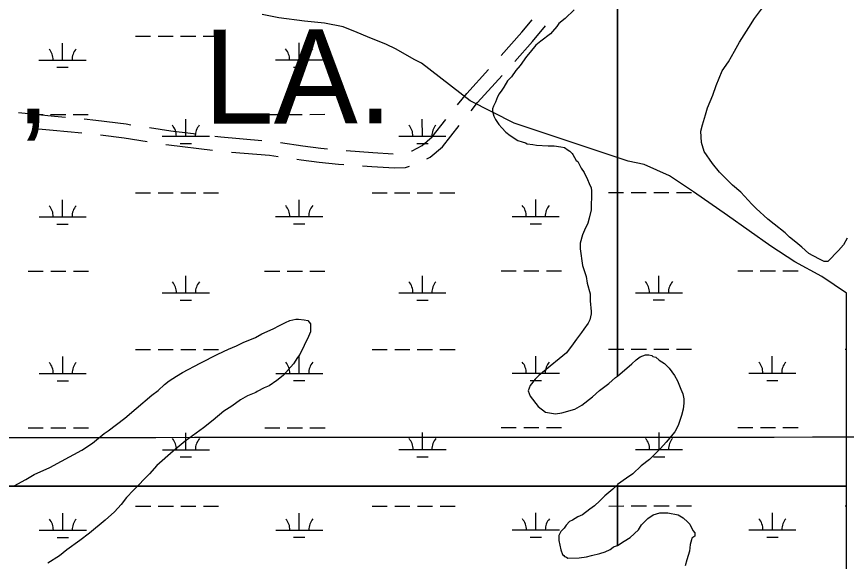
# Model space of a CAD drawing. Extents: x 3279314 to 3317160, y 734079 to 759431.
# Drawn here: x 3299638 to 3301399, y 745259 to 746416 of the extents above; entities that cross this region are included whole.
import ezdxf

# ---------------------------------------------------------------- set-up
doc = ezdxf.new("R2010")
doc.units = 0
for name, color, linetype in [('V-GRID-MAJR', 7, 'Continuous'), ('V-ROAD-CNTR', 7, 'Continuous'), ('V-SITE-VEGE', 7, 'Continuous'), ('V-TOPO-GNAM-IDEN', 7, 'Continuous'), ('V-WETL-SWMP', 7, 'Continuous')]:
    doc.layers.add(name, color=color, linetype=linetype)

msp = doc.modelspace()

# ---------------------------------------------------------------- linework, layer by layer
at = {"layer": 'V-GRID-MAJR'}
msp.add_spline([(3283456.6, 745517.7), (3286079.8, 745518), (3291326.2, 745519.1), (3296572.6, 745521), (3301819.1, 745523.7), (3307065.5, 745527.1), (3312312, 745531.3), (3314935.2, 745533.7)], degree=3, dxfattribs=at)
at = {"layer": 'V-ROAD-CNTR'}
for points in [[(3300666.3, 746333.6), (3300710.1, 746382.6), (3300731.9, 746409.1)], [(3300695.1, 746320.9), (3300732.8, 746363.1), (3300760.4, 746396.5)], [(3300573.9, 746228.5), (3300593.6, 746252.8), (3300639.6, 746303.9)], [(3300602.4, 746216), (3300616.4, 746233.3), (3300668.4, 746291.1)], [(3299642.2, 746212.2), (3299718.8, 746204.7), (3299741.7, 746202.5)], [(3299781.5, 746198.6), (3299806.1, 746196.3), (3299870.4, 746188), (3299880.7, 746186.4)], [(3300476.2, 746130.9), (3300477.2, 746131.2), (3300498.6, 746142.5), (3300519.9, 746160.3), (3300548.9, 746197.2)], [(3299677.1, 746178.6), (3299715.9, 746174.8), (3299776.6, 746169)], [(3299920.3, 746180.2), (3299965.1, 746173.2), (3300019.3, 746166.7)], [(3300508.3, 746113.7), (3300515.4, 746117.4), (3300541.6, 746139.3), (3300577.3, 746184.8)], [(3299816.3, 746164.7), (3299866.2, 746158.3), (3299915.3, 746150.6)], [(3300059, 746161.9), (3300071.6, 746160.4), (3300158.6, 746153)], [(3299954.8, 746144.4), (3299961, 746143.5), (3300054.1, 746132.3)], [(3300198.3, 746148.4), (3300245.7, 746141.5), (3300283.7, 746136.8), (3300297.5, 746135.4)], [(3300093.9, 746128.4), (3300174.6, 746121.6), (3300193.4, 746118.8)], [(3300337.3, 746131.8), (3300393.9, 746127.5), (3300437, 746124.8)], [(3300233, 746113), (3300241.7, 746111.8), (3300280.4, 746107), (3300320.9, 746102.9), (3300332.3, 746102.1)], [(3300372.2, 746099.1), (3300391.8, 746097.6), (3300439.7, 746094.6), (3300463.6, 746095.6), (3300471.7, 746098.1)]]:
    msp.add_lwpolyline(points, dxfattribs=at)
at = {"layer": 'V-SITE-VEGE'}
for points in [[(3300822.9, 745582.3), (3300837.5, 745590.7), (3300860.3, 745608.6), (3300874.9, 745622.2), (3300894.6, 745636.9), (3300909.1, 745649.4), (3300912.9, 745652.7), (3300912.9, 746541)], [(3300912.9, 746541), (3300912.9, 745652.7), (3300943.4, 745678.8), (3300952.7, 745687.2), (3300961, 745693.5), (3300972.4, 745697.7), (3300979.7, 745697.7), (3300986, 745696.7), (3300988.1, 745694.6), (3300994.4, 745692.6), (3301001.7, 745686.4), (3301013.2, 745679.1), (3301022.6, 745669.8), (3301034.1, 745654.2), (3301040.4, 745642.8), (3301047.8, 745625.1), (3301052, 745614.7), (3301054.2, 745604.3), (3301054.2, 745594.9), (3301052.2, 745582.4), (3301049.1, 745568.8), (3301041.9, 745548), (3301034.7, 745534.4), (3301016.1, 745512.4), (3301004.7, 745498.8), (3300980.8, 745475.8), (3300963.2, 745462.1), (3300945.5, 745445.4), (3300932, 745435.9), (3300913.3, 745422.3), (3300912.9, 745421.9), (3300912.9, 745293.3), (3300927.4, 745302.5), (3300939.9, 745309.9), (3300957.6, 745326.6), (3300963.8, 745337.1), (3300977.2, 745350.7), (3300988.7, 745358), (3301003.2, 745362.3), (3301019.9, 745362.4), (3301041.8, 745358.3), (3301052.3, 745352.1), (3301062.7, 745342.8), (3301066.9, 745338.6), (3301073.2, 745325.1), (3301077.4, 745319.9), (3301077.5, 745312.6), (3301071.2, 745308.4), (3301070.2, 745305.3), (3301067.1, 745294.9), (3301066.1, 745281.3), (3301060, 745262.5), (3301056.9, 745250)], [(3300821, 746430.6), (3300802.3, 746411.7), (3300788.8, 746401.2), (3300784.7, 746395), (3300775.3, 746384.5), (3300771.2, 746379.3), (3300750.4, 746363.5), (3300740, 746355.2), (3300727.6, 746340.5), (3300720.4, 746331.1), (3300706.9, 746312.3), (3300697.6, 746301.8), (3300688.3, 746288.2), (3300680, 746279.8), (3300671.7, 746266.3), (3300667.6, 746260), (3300662.4, 746251.6), (3300658.2, 746245.3), (3300654.1, 746233.9), (3300650, 746225.5), (3300647.9, 746220.3), (3300648, 746215.1), (3300651.1, 746204.7), (3300654.3, 746197.4), (3300661.6, 746187), (3300667.9, 746179.7), (3300676.3, 746170.4), (3300685.7, 746163.2), (3300701.4, 746152.8), (3300710.8, 746149.7), (3300718.1, 746147.7), (3300721.2, 746145.6), (3300733.8, 746144.6), (3300741.1, 746142.6), (3300766.1, 746141.7), (3300778.6, 746141.7), (3300793.2, 746139.7), (3300800.5, 746137.7), (3300808.8, 746132.5), (3300812, 746130.4), (3300817.2, 746125.2), (3300818.3, 746123.2), (3300825.6, 746110.7), (3300828.8, 746108.6), (3300836.1, 746094.1), (3300842.4, 746084.7), (3300849.8, 746070.2), (3300852.9, 746061.8), (3300857.2, 746052.5), (3300858.2, 746046.2), (3300858.3, 746030.6), (3300857.3, 746019.1), (3300857.4, 746005.6), (3300853.3, 745987.8), (3300850.2, 745977.4), (3300843, 745962.8), (3300838.9, 745952.3), (3300833.8, 745934.6), (3300833.8, 745923.1), (3300839.2, 745887.7), (3300846.6, 745863.8), (3300848.8, 745850.3), (3300855.1, 745827.4), (3300855.2, 745812.8), (3300857.4, 745789.9), (3300857.4, 745784.7), (3300854.3, 745772.1), (3300851.2, 745764.8), (3300841.9, 745752.3), (3300836.8, 745745), (3300826.4, 745731.4), (3300819.2, 745720.9), (3300804.7, 745702.1), (3300789.1, 745689.5), (3300770.4, 745673.8), (3300762.1, 745666.5), (3300746.5, 745653.9), (3300738.2, 745646.5), (3300727.9, 745632.9), (3300723.8, 745621.5), (3300728, 745610), (3300744.8, 745588.2), (3300760.5, 745575.8), (3300781.3, 745572.8), (3300794.8, 745574.9), (3300822.9, 745582.3)], [(3301400.5, 745945.2), (3301392.6, 745931.7), (3301382, 745919.4), (3301359.5, 745896.3), (3301351.4, 745896.2), (3301343.3, 745900.1), (3301328.4, 745908), (3301318.9, 745913.2), (3301304, 745926.5), (3301291.7, 745937.1), (3301278.2, 745947.7), (3301268.6, 745957), (3301245.6, 745975.5), (3301232, 745986.1), (3301207.5, 746008.6), (3301198, 746017.9), (3301174.8, 746043.2), (3301157.1, 746057.7), (3301129.9, 746085.6), (3301114.9, 746104.2), (3301097.1, 746129.6), (3301091.5, 746148.3), (3301089.8, 746172.5), (3301093.7, 746186), (3301100.1, 746207.6), (3301104, 746222.4), (3301115.7, 746249.4), (3301122.2, 746269.7), (3301135.2, 746300.8), (3301148.5, 746319.8), (3301161.6, 746342.8), (3301172.1, 746361.7), (3301191.9, 746392.9), (3301203.7, 746411.9), (3301224.9, 746440.4)], [(3299990.2, 745660.1), (3300027.6, 745680.1), (3300065, 745699), (3300087.9, 745709.6), (3300104.5, 745716.9), (3300119.1, 745724.3), (3300145.1, 745734.8), (3300158.6, 745742.2), (3300182.5, 745752.7), (3300196, 745760.1), (3300208.5, 745766.4), (3300217.9, 745770.6), (3300230.3, 745773.8), (3300236.6, 745773.8), (3300248.1, 745771.8), (3300256.4, 745770.8), (3300261.7, 745763.5), (3300261.7, 745746.9), (3300257.6, 745736.4), (3300239, 745698.8), (3300233.9, 745692.5), (3300225.6, 745679), (3300203.8, 745653.8), (3300190.3, 745643.4), (3300173.7, 745631.8), (3300163.3, 745627.6), (3300148.8, 745620.2), (3300145.6, 745618.1), (3300128, 745610.7), (3300113.4, 745602.3), (3300094.7, 745588.7), (3300078.1, 745578.2), (3300055.3, 745559.3), (3300034.5, 745542.6), (3299996.1, 745514.2), (3299970.1, 745493.3), (3299935.9, 745462.9), (3299920.3, 745445.1), (3299886.1, 745410.6), (3299871.6, 745394.9), (3299860.2, 745380.2), (3299845.7, 745364.5), (3299826, 745346.7), (3299792.8, 745319.4), (3299772, 745303.7), (3299745, 745283.8), (3299729.4, 745271.2), (3299704.5, 745255.5)], [(3299632.9, 745419.8), (3299657.8, 745433.4), (3299675.5, 745443.9), (3299708.7, 745458.7), (3299733.7, 745472.3), (3299776.3, 745495.5), (3299799.1, 745510.2), (3299824.1, 745531.1), (3299832.4, 745536.4), (3299867.7, 745563.6), (3299891.5, 745583.6), (3299924.8, 745611.9), (3299938.2, 745622.3), (3299951.7, 745634.9), (3299962.1, 745642.3), (3299977.7, 745652.8), (3299990.2, 745660.1)]]:
    msp.add_lwpolyline(points, dxfattribs=at)
msp.add_lwpolyline([(3300912.9, 745421.9), (3300903, 745412.9), (3300886.3, 745398.2), (3300876, 745387.7), (3300864.6, 745377.3), (3300854.2, 745369.9), (3300838.6, 745358.4), (3300829.2, 745354.2), (3300817.8, 745346.8), (3300811.6, 745343.7), (3300804.3, 745336.3), (3300800.2, 745330.1), (3300792.9, 745322.7), (3300788.8, 745314.4), (3300788.8, 745303.9), (3300793.1, 745284.2), (3300796.3, 745273.8), (3300799.4, 745271.7), (3300800.5, 745269.6), (3300804.6, 745268.6), (3300807.8, 745266.5), (3300831.7, 745266.6), (3300847.4, 745268.8), (3300857.8, 745272), (3300875.5, 745276.2), (3300886.9, 745279.4), (3300897.3, 745284.7), (3300900.4, 745286.8), (3300904.6, 745289.9), (3300910.8, 745292), (3300912.9, 745293.3)], close=True, dxfattribs=at)
at = {"layer": 'V-WETL-SWMP'}
for p, q in [((3299890.2, 746374.4), (3299922.2, 746374.4)), ((3299938.2, 746374.4), (3299970.2, 746374.5)), ((3299986.2, 746374.5), (3300018.2, 746374.5)), ((3300034.2, 746374.5), (3300066.2, 746374.5)), ((3299735.6, 746323.6), (3299735.6, 746359.6)), ((3300237.5, 746323.9), (3300237.5, 746359.9)), ((3299685.6, 746323.6), (3299785.6, 746323.6)), ((3300187.5, 746323.8), (3300287.5, 746323.9)), ((3299723.6, 746308.2), (3299747.6, 746308.2)), ((3300225.6, 746308.4), (3300249.6, 746308.4)), ((3299662.3, 746208.1), (3299694.3, 746208.1)), ((3299710.3, 746208.2), (3299742.3, 746208.2)), ((3299758.3, 746208.2), (3299790.3, 746208.2)), ((3299997.2, 746161.9), (3299997.1, 746197.9)), ((3300164.2, 746208.4), (3300196.2, 746208.4)), ((3300212.2, 746208.4), (3300244.2, 746208.4)), ((3300260.2, 746208.4), (3300292.2, 746208.5)), ((3300499.1, 746162.1), (3300499, 746198.1)), ((3299947.2, 746161.8), (3300047.2, 746161.9)), ((3300449.1, 746162.1), (3300549.1, 746162.2)), ((3299985.2, 746146.4), (3300009.2, 746146.4)), ((3300487.1, 746146.7), (3300511.1, 746146.7)), ((3299890.4, 746041.7), (3299922.4, 746041.8)), ((3299938.4, 746041.8), (3299970.4, 746041.8)), ((3299986.4, 746041.8), (3300018.4, 746041.8)), ((3300034.4, 746041.8), (3300066.4, 746041.8)), ((3300392.3, 746042), (3300424.3, 746042)), ((3300440.3, 746042), (3300472.3, 746042)), ((3300488.3, 746042.1), (3300520.3, 746042.1)), ((3300536.3, 746042.1), (3300568.3, 746042.1)), ((3300894.2, 746042.3), (3300926.2, 746042.3)), ((3300942.2, 746042.3), (3300974.2, 746042.3)), ((3300990.2, 746042.3), (3301022.2, 746042.3)), ((3301038.2, 746042.3), (3301070.2, 746042.3)), ((3299735.8, 745990.9), (3299735.8, 746026.9)), ((3300237.7, 745991.2), (3300237.7, 746027.2)), ((3300739.6, 745991.4), (3300739.6, 746027.4)), ((3299685.8, 745990.9), (3299785.8, 745991)), ((3300187.7, 745991.2), (3300287.7, 745991.2)), ((3300689.6, 745991.4), (3300789.6, 745991.5)), ((3299723.8, 745975.5), (3299747.8, 745975.5)), ((3300225.7, 745975.7), (3300249.7, 745975.8)), ((3300727.6, 745976), (3300751.6, 745976)), ((3299662.5, 745875.5), (3299694.5, 745875.5)), ((3299710.5, 745875.5), (3299742.5, 745875.5)), ((3299758.5, 745875.5), (3299790.5, 745875.5)), ((3299997.3, 745829.2), (3299997.3, 745865.2)), ((3300164.4, 745875.7), (3300196.4, 745875.7)), ((3300212.4, 745875.7), (3300244.4, 745875.8)), ((3300260.4, 745875.8), (3300292.4, 745875.8)), ((3300499.2, 745829.5), (3300499.2, 745865.5)), ((3300666.3, 745876), (3300698.3, 745876)), ((3300714.3, 745876), (3300746.3, 745876)), ((3300762.3, 745876), (3300794.3, 745876)), ((3301001.1, 745829.7), (3301001.1, 745865.7)), ((3301168.2, 745876.2), (3301200.2, 745876.2)), ((3301216.2, 745876.2), (3301248.2, 745876.3)), ((3301264.2, 745876.3), (3301296.2, 745876.3)), ((3299947.3, 745829.2), (3300047.3, 745829.2)), ((3300449.2, 745829.4), (3300549.2, 745829.5)), ((3300951.1, 745829.7), (3301051.1, 745829.7)), ((3299985.3, 745813.8), (3300009.3, 745813.8)), ((3300487.2, 745814), (3300511.2, 745814)), ((3300989.1, 745814.3), (3301013.1, 745814.3)), ((3299890.5, 745709.1), (3299922.5, 745709.1)), ((3299938.5, 745709.1), (3299970.5, 745709.1)), ((3299986.5, 745709.1), (3300018.5, 745709.1)), ((3300034.5, 745709.1), (3300066.5, 745709.2)), ((3300392.4, 745709.3), (3300424.4, 745709.3)), ((3300440.4, 745709.4), (3300472.4, 745709.4)), ((3300488.4, 745709.4), (3300520.4, 745709.4)), ((3300536.4, 745709.4), (3300568.4, 745709.4)), ((3300894.4, 745709.6), (3300926.4, 745709.6)), ((3300942.4, 745709.6), (3300974.4, 745709.6)), ((3300990.4, 745709.6), (3301022.4, 745709.6)), ((3301038.4, 745709.7), (3301070.4, 745709.7)), ((3301396.3, 745709.8), (3301398.9, 745709.8)), ((3299736, 745658.3), (3299736, 745694.3)), ((3300237.9, 745658.5), (3300237.9, 745694.5)), ((3300739.8, 745658.8), (3300739.8, 745694.8)), ((3301241.7, 745659), (3301241.7, 745695)), ((3299686, 745658.2), (3299786, 745658.3)), ((3300187.9, 745658.5), (3300287.9, 745658.5)), ((3300689.8, 745658.7), (3300789.8, 745658.8)), ((3301191.7, 745659), (3301291.7, 745659)), ((3299724, 745642.8), (3299748, 745642.8)), ((3300225.9, 745643.1), (3300249.9, 745643.1)), ((3300727.8, 745643.3), (3300751.8, 745643.3)), ((3301229.7, 745643.6), (3301253.7, 745643.6)), ((3299662.6, 745542.8), (3299694.6, 745542.8)), ((3299710.6, 745542.8), (3299742.6, 745542.8)), ((3299758.6, 745542.8), (3299790.6, 745542.8)), ((3299997.5, 745496.5), (3299997.5, 745532.5)), ((3300164.5, 745543), (3300196.5, 745543.1)), ((3300212.5, 745543.1), (3300244.5, 745543.1)), ((3300260.5, 745543.1), (3300292.5, 745543.1)), ((3300499.4, 745496.8), (3300499.4, 745532.8)), ((3300666.4, 745543.3), (3300698.4, 745543.3)), ((3300714.4, 745543.3), (3300746.4, 745543.3)), ((3300762.4, 745543.3), (3300794.4, 745543.4)), ((3301001.3, 745497), (3301001.3, 745533)), ((3301168.3, 745543.5), (3301200.3, 745543.6)), ((3301216.3, 745543.6), (3301248.3, 745543.6)), ((3301264.3, 745543.6), (3301296.3, 745543.6)), ((3299947.5, 745496.5), (3300047.5, 745496.5)), ((3300449.4, 745496.8), (3300549.4, 745496.8)), ((3300951.3, 745497), (3301051.3, 745497.1)), ((3299985.5, 745481.1), (3300009.5, 745481.1)), ((3300487.4, 745481.3), (3300511.4, 745481.4)), ((3300989.3, 745481.6), (3301013.3, 745481.6)), ((3301398.9, 745419.1), (3294985.1, 745419)), ((3301398.9, 745419.1), (3294985.1, 745419)), ((3301398.9, 744248.6), (3301398.9, 745419.1)), ((3301398.9, 744248.6), (3301398.9, 745419.1)), ((3299890.7, 745376.4), (3299922.7, 745376.4)), ((3299938.7, 745376.5), (3299970.7, 745376.5)), ((3299986.7, 745376.5), (3300018.7, 745376.5)), ((3300034.7, 745376.5), (3300066.7, 745376.5)), ((3300392.6, 745376.7), (3300424.6, 745376.7)), ((3300440.6, 745376.7), (3300472.6, 745376.7)), ((3300488.6, 745376.7), (3300520.6, 745376.7)), ((3300536.6, 745376.8), (3300568.6, 745376.8)), ((3300894.5, 745376.9), (3300926.5, 745377)), ((3300942.5, 745377), (3300974.5, 745377)), ((3300990.5, 745377), (3301022.5, 745377)), ((3301038.5, 745377), (3301070.5, 745377)), ((3301396.4, 745377.2), (3301398.9, 745377.2)), ((3299736.1, 745325.6), (3299736.1, 745361.6)), ((3300238, 745325.9), (3300238, 745361.9)), ((3300739.9, 745326.1), (3300739.9, 745362.1)), ((3301241.8, 745326.4), (3301241.8, 745362.4)), ((3299686.1, 745325.6), (3299786.1, 745325.6)), ((3300188, 745325.8), (3300288, 745325.9)), ((3300689.9, 745326.1), (3300789.9, 745326.1)), ((3301191.8, 745326.3), (3301291.8, 745326.4)), ((3299724.1, 745310.2), (3299748.1, 745310.2)), ((3300226, 745310.4), (3300250, 745310.4)), ((3300727.9, 745310.7), (3300751.9, 745310.7)), ((3301229.8, 745310.9), (3301253.8, 745310.9))]:
    msp.add_line(p, q, dxfattribs=at)
msp.add_lwpolyline([(3294985.1, 745419), (3301398.9, 745419), (3301398.9, 745828.8), (3301346.9, 745864), (3301289.2, 745895.5), (3301238.5, 745928.2), (3301146.5, 745993.6), (3301074.5, 746043.8), (3301023.8, 746077.6), (3300969.6, 746102), (3300935.5, 746108.9), (3300694.1, 746190), (3300600.3, 746237.2), (3300497.2, 746317.2), (3300483.1, 746324.2), (3300441.8, 746347.5), (3300423, 746356.8), (3300382.9, 746373.1), (3300360.5, 746382.4), (3300331.1, 746394), (3300291.1, 746402.1), (3300248.8, 746406.5), (3300194.6, 746413.3), (3300159.4, 746420.2)], dxfattribs=at)
msp.add_lwpolyline([(3294985.1, 745419), (3301398.9, 745419), (3301398.9, 745828.8), (3301346.9, 745864), (3301289.2, 745895.5), (3301238.5, 745928.2), (3301146.5, 745993.6), (3301074.5, 746043.8), (3301023.8, 746077.6), (3300969.6, 746102), (3300935.5, 746108.9), (3300694.1, 746190), (3300600.3, 746237.2), (3300497.2, 746317.2), (3300483.1, 746324.2), (3300441.8, 746347.5), (3300423, 746356.8), (3300382.9, 746373.1), (3300360.5, 746382.4), (3300331.1, 746394), (3300291.1, 746402.1), (3300248.8, 746406.5), (3300194.6, 746413.3), (3300159.4, 746420.2)], dxfattribs=at)
for centre, start, end in [((3299680.4, 746324), 359.2573, 40.801), ((3299790.9, 746324.1), 139.2573, 180.801), ((3300182.3, 746324.3), 359.2573, 40.801), ((3300292.8, 746324.4), 139.2573, 180.801), ((3299941.9, 746162.3), 359.2573, 40.801), ((3300052.4, 746162.4), 139.2573, 180.801), ((3300443.8, 746162.6), 359.2573, 40.801), ((3300554.3, 746162.6), 139.2573, 180.801), ((3299680.6, 745991.4), 359.2573, 40.801), ((3299791, 745991.4), 139.2573, 180.801), ((3300182.5, 745991.6), 359.2573, 40.801), ((3300293, 745991.7), 139.2573, 180.801), ((3300684.4, 745991.9), 359.2573, 40.801), ((3300794.9, 745991.9), 139.2573, 180.801), ((3299942.1, 745829.6), 359.2573, 40.801), ((3300052.6, 745829.7), 139.2573, 180.801), ((3300444, 745829.9), 359.2573, 40.801), ((3300554.5, 745830), 139.2573, 180.801), ((3300945.9, 745830.2), 359.2573, 40.801), ((3301056.4, 745830.2), 139.2573, 180.801), ((3299680.7, 745658.7), 359.2573, 40.801), ((3299791.2, 745658.8), 139.2573, 180.801), ((3300182.6, 745659), 359.2573, 40.801), ((3300293.1, 745659), 139.2573, 180.801), ((3300684.5, 745659.2), 359.2573, 40.801), ((3300795, 745659.3), 139.2573, 180.801), ((3301186.5, 745659.5), 359.2573, 40.801), ((3301296.9, 745659.5), 139.2573, 180.801), ((3299942.2, 745497), 359.2573, 40.801), ((3300052.7, 745497), 139.2573, 180.801), ((3300444.2, 745497.2), 359.2573, 40.801), ((3300554.6, 745497.3), 139.2573, 180.801), ((3300946.1, 745497.5), 359.2573, 40.801), ((3301056.6, 745497.5), 139.2573, 180.801), ((3299680.9, 745326.1), 359.2573, 40.801), ((3299791.3, 745326.1), 139.2573, 180.801), ((3300182.8, 745326.3), 359.2573, 40.801), ((3300293.3, 745326.4), 139.2573, 180.801), ((3300684.7, 745326.6), 359.2573, 40.801), ((3300795.2, 745326.6), 139.2573, 180.801), ((3301186.6, 745326.8), 359.2573, 40.801), ((3301297.1, 745326.9), 139.2573, 180.801)]:
    msp.add_arc(centre, 35.2, start, end, dxfattribs=at)

# ---------------------------------------------------------------- texts
at = {"layer": 'V-TOPO-GNAM-IDEN'}
for s, p in [('PARISH,', (3298640.1, 746187.1)), ('LA.', (3300035.1, 746188.4))]:
    msp.add_text(s, height=200, rotation=0.1349, dxfattribs=at).set_placement(p)

doc.saveas('drawing.dxf')
